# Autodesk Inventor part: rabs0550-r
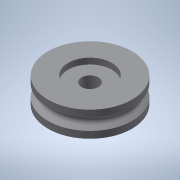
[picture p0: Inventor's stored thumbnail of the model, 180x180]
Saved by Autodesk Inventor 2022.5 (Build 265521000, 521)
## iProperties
Created: 2016-12
Part Number: rabs0550-r
Material: 一般
Document SubType Name: Modeling
Designer: imaocorp
Density: 1 g/cm^3
Appearance: 既定
Author: imaocorp
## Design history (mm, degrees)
node "rabs0550-r.x_t1"
node "rabs0550-r"
node "Base1"
